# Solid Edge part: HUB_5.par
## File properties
Author: Türk
Template: Iso Part.par
Last saved by: Türk
Revision: 13
Application: Solid Edge
Accuracy: 0,990
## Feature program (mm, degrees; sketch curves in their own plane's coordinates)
thread "unnamed Thread 1"
pattern "unnamed Pattern 1" of "unnamed Thread 1"
pattern "PatternOccurrence_2"  XOffset = 72 deg
thread "unnamed Thread 2"
thread "unnamed Thread 3"
thread "unnamed Thread 4"
thread "unnamed Thread 5"
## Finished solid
Body 1: solid body, 49 faces, 91 edges, 44 vertices.
  Faces by surface: cylinder 29, plane 20
  Edges by curve: circle 53, line 38
Bounding box of the edges (mm): 110.451 x 225.000 x 115.106, from (-60, -150, -57.5528) to (50.4508, 75, 57.5528).
Cylindrical faces by radius (mm): R6 x10, R7.5 x2, R10 x9, R27.5 x1, R32 x1, R40 x1, R50 x5
Planar faces by outward normal: +x 2, +y 7, +z 2, -x 2, -y 5, -z 2
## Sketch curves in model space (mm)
line (0, -40, 32) -> (0, -40, -32)
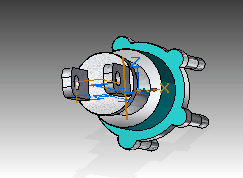
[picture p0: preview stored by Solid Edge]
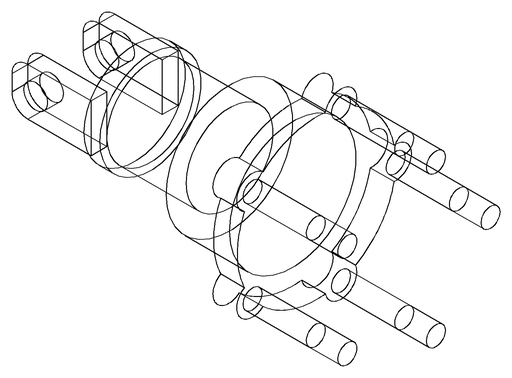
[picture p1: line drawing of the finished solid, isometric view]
